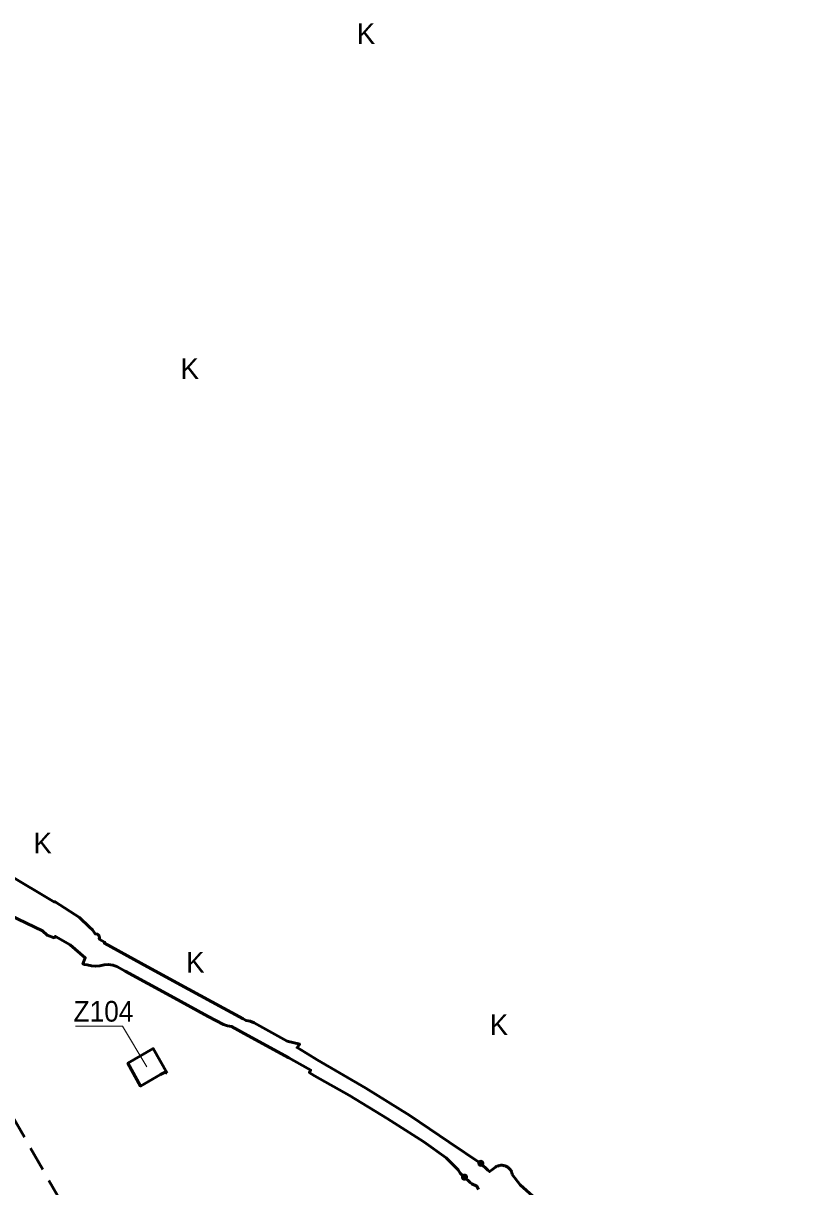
# Model space of a CAD drawing. Extents: x -650246 to -642674, y -1074280 to -1066767.
# Drawn here: x -646112 to -645200, y -1069193 to -1067841 of the extents above; entities that cross this region are included whole.
import ezdxf

# ---------------------------------------------------------------- set-up
doc = ezdxf.new("R2010")
doc.units = 0
doc.header["$LTSCALE"] = 9.6
doc.header["$PDMODE"] = 32
doc.header["$PDSIZE"] = 4.8
doc.linetypes.add('MEDIUM_DASHED', pattern=[4.5, 3, -1.5])
for name, color, linetype, lineweight in [('44', 7, 'Continuous', 53), ('45', 7, 'Continuous', 53), ('46', 7, 'Continuous', 13), ('48', 7, 'Continuous', 13), ('61', 7, 'MEDIUM_DASHED', 53)]:
    doc.layers.add(name, color=color, linetype=linetype, lineweight=lineweight)

msp = doc.modelspace()

# ---------------------------------------------------------------- linework, layer by layer
at = {"layer": '44'}
for points in [[(-645579.94, -1069165.52), (-645616.63, -1069140.8), (-645662.44, -1069109.89), (-645713.61, -1069078.06), (-645770.04, -1069045.34), (-645773.38, -1069043.46), (-645793.638, -1069031.021), (-645790.53, -1069027.19), (-645805.16, -1069023.52), (-645843.56, -1069002.41), (-645848.18, -1069000.48), (-645852.91, -1068999.62), (-645856.26, -1068997.79), (-645892.77, -1068977.86), (-645933.28, -1068955.74), (-645975.31, -1068932.8), (-646017.55, -1068909.75), (-646017.39, -1068908.42), (-646023.56, -1068905.05), (-646023.13, -1068903.12), (-646023.92, -1068900.73), (-646025.57, -1068899.39), (-646028.18, -1068898.89), (-646031.31, -1068894.32), (-646034.65, -1068891.12), (-646046.48, -1068879.92), (-646074.78, -1068861.51), (-646075.56, -1068861.95), (-646130.68, -1068829.21)], [(-646137.23, -1068872.6), (-646089.63, -1068895.5), (-646084.1, -1068900.51), (-646076.09, -1068903.48), (-646074.51, -1068901.9), (-646057.13, -1068911.62), (-646039.84, -1068926.67), (-646042.5, -1068933.91), (-646040.65, -1068934.59), (-646037.5, -1068934.7), (-646032.61, -1068936.1)], [(-646032.61, -1068936.1), (-646027.69, -1068936.6), (-646022.77, -1068936.12), (-646017.6, -1068934.89), (-646012.64, -1068934.34), (-646007.7, -1068935.18), (-646002.95, -1068936.95), (-645993.5, -1068942.1), (-645940.77, -1068970.74), (-645896.91, -1068994.75), (-645879.17, -1069004.02), (-645874.49, -1069005.73), (-645869.83, -1069006.45), (-645850.79, -1069016.84), (-645803.29, -1069042.92), (-645781.12, -1069055.29), (-645777.73, -1069057.2), (-645779.49, -1069059.92), (-645773.29, -1069063.99), (-645732.65, -1069086.82), (-645688.87, -1069113.44), (-645646.08, -1069140.37), (-645620.2, -1069159.26), (-645606.11, -1069172.98), (-645603.91, -1069176.86), (-645599, -1069181.48)], [(-645571.9, -1069173.43), (-645579.94, -1069165.52), (-645579.94, -1069165.52)], [(-645543.43, -1069178.39), (-645543.547, -1069177.727), (-645543.706, -1069177.053), (-645543.907, -1069176.37), (-645544.154, -1069175.682), (-645544.448, -1069174.993), (-645544.792, -1069174.308), (-645545.186, -1069173.63), (-645545.631, -1069172.966), (-645546.127, -1069172.32), (-645546.674, -1069171.699), (-645547.269, -1069171.107), (-645547.91, -1069170.551), (-645548.594, -1069170.034), (-645549.317, -1069169.563), (-645550.076, -1069169.141), (-645550.863, -1069168.772), (-645551.674, -1069168.459), (-645552.504, -1069168.203), (-645553.344, -1069168.007), (-645554.191, -1069167.87), (-645555.036, -1069167.793), (-645555.875, -1069167.772), (-645556.702, -1069167.808), (-645557.511, -1069167.896), (-645558.298, -1069168.035), (-645559.06, -1069168.219), (-645559.793, -1069168.445), (-645560.494, -1069168.709), (-645561.162, -1069169.007), (-645561.794, -1069169.334), (-645562.39, -1069169.686), (-645562.95, -1069170.06), (-645567.5, -1069173.46), (-645569.81, -1069175.03), (-645571.9, -1069173.43)], [(-645184.88, -1069596.58), (-645202.56, -1069568.23), (-645230.1, -1069525.98), (-645253.4, -1069493.06), (-645278.31, -1069461.33), (-645281.4, -1069458.4), (-645290.5, -1069449.03), (-645299.61, -1069437.97), (-645306.16, -1069425.55), (-645314.14, -1069412.54), (-645321.1, -1069405.21), (-645326.59, -1069396.64), (-645350.63, -1069363.98), (-645371.12, -1069339.47), (-645376.38, -1069332.65), (-645400.07, -1069313.32), (-645424.8, -1069295.24), (-645458.45, -1069265.56), (-645494.13, -1069227.63), (-645515.89, -1069206.66), (-645534.25, -1069190.56), (-645543.43, -1069178.39)], [(-645599, -1069181.48), (-645599, -1069181.48), (-645592.24, -1069187.73), (-645590.41, -1069189.45), (-645584.73, -1069191.88), (-645582.63, -1069195.88)]]:
    msp.add_lwpolyline(points, dxfattribs=at)
for p in [(-645579.94, -1069165.52), (-645599, -1069181.48)]:
    msp.add_point(p, dxfattribs=at)
at = {"layer": '45'}
for points in [[(-645944.69, -1069060.7), (-645960.67, -1069032.26), (-645990.13, -1069049.3), (-645975.48, -1069075.71), (-645952.21, -1069062.4)], [(-645944.69, -1069060.7), (-645960.67, -1069032.26), (-645990.13, -1069049.3), (-645975.48, -1069075.71), (-645952.21, -1069062.4)], [(-645952.21, -1069062.4), (-645946.84, -1069059.58), (-645944.69, -1069060.7)], [(-645952.21, -1069062.4), (-645946.84, -1069059.58), (-645944.69, -1069060.7)]]:
    msp.add_lwpolyline(points, dxfattribs=at)
at = {"layer": '46'}
msp.add_lwpolyline([(-646051.21, -1069006.26), (-645996.286, -1069006.26), (-645968.211, -1069053.466)], dxfattribs=at)
msp.add_lwpolyline([(-646051.21, -1069006.26), (-645996.286, -1069006.26), (-645968.211, -1069053.466)], dxfattribs=at)
at = {"layer": '61'}
msp.add_lwpolyline([(-646583.457, -1069759.191), (-646554.262, -1069762.602), (-646321.973, -1069686.855), (-646209.9, -1069538.5), (-646146.8, -1069506.6), (-646148.5, -1069503), (-646028.16, -1069441.58), (-646023.96, -1069440.34), (-646075.49, -1069318.19), (-646025.14, -1069285.394), (-646153.307, -1069059.947)], dxfattribs=at)

# ---------------------------------------------------------------- texts
at = {"layer": '46', "width": 0.95}
msp.add_text('Z104', height=24, dxfattribs=at).set_placement((-646053.286, -1069000.877))
msp.add_text('Z104', height=24, dxfattribs=at).set_placement((-646053.286, -1069000.877))
at = {"layer": '48'}
for p in [(-645724.189, -1067865.057), (-645724.189, -1067865.057), (-645928.983, -1068254.123), (-645928.983, -1068254.123), (-646099.972, -1068805.526), (-645922.543, -1068943.866), (-645922.543, -1068943.866), (-645569.606, -1069016.557), (-645569.606, -1069016.557)]:
    msp.add_text('K', height=24, dxfattribs=at).set_placement(p)

doc.saveas('drawing.dxf')
